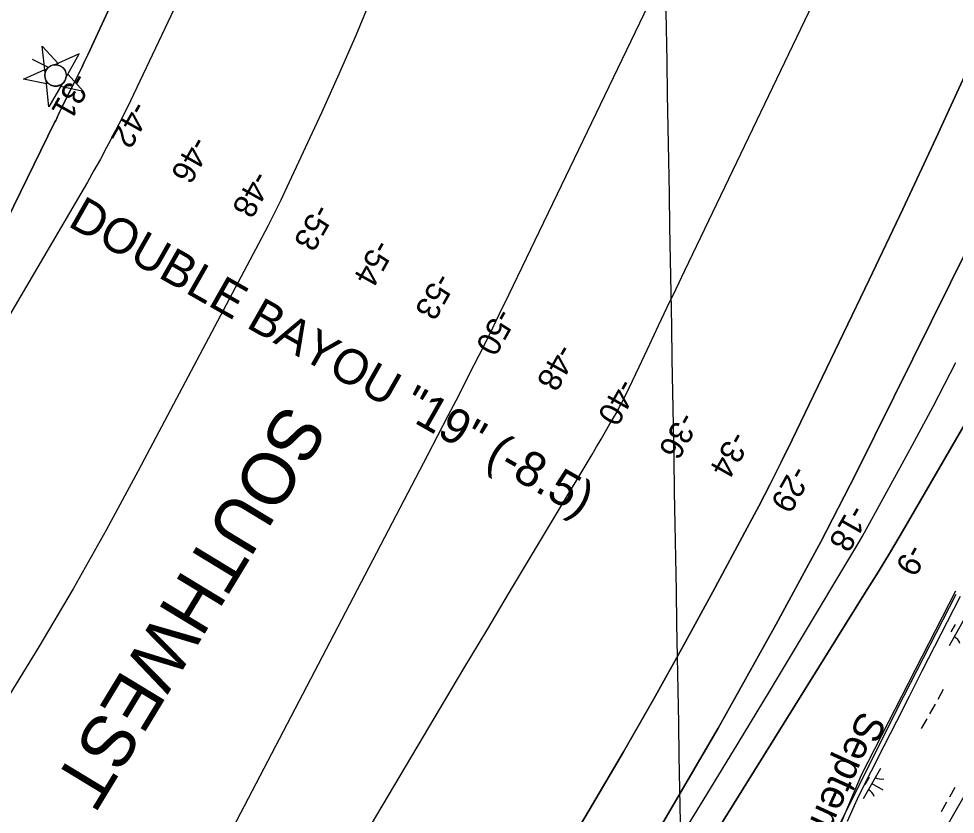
# Model space of a CAD drawing. Extents: x 3913936 to 3933962, y 195330 to 217741.
# Drawn here: x 3924311 to 3925651, y 203527 to 204666 of the extents above; entities that cross this region are included whole.
import ezdxf

# ---------------------------------------------------------------- set-up
doc = ezdxf.new("R2010")
doc.units = 0
for name, color, linetype in [('V-CHAN-NAID', 7, 'Continuous'), ('V-GRID-MAJR', 7, 'Continuous'), ('V-LEVE-TOET', 7, 'Continuous'), ('V-RIVR-EDGE', 7, 'Continuous'), ('V-RIVR-IDEN', 7, 'Continuous'), ('V-RIVR-RANG', 7, 'Continuous'), ('V-RRAP-FSHR', 7, 'Continuous'), ('V-TOPO-DPTH', 7, 'Continuous'), ('V-TOPO-MAJR', 7, 'Continuous'), ('V-TOPO-MINR', 7, 'Continuous'), ('V-UTIL-LINE', 7, 'Continuous'), ('V-WETL-SWMP', 7, 'Continuous')]:
    doc.layers.add(name, color=color, linetype=linetype)

msp = doc.modelspace()

# ---------------------------------------------------------------- linework, layer by layer
at = {"layer": 'V-CHAN-NAID'}
for points in [[(3924348.6, 204588.4), (3924344.4, 204626.5), (3924367, 204601.7), (3924362.6, 204599.7), (3924362, 204599.7), (3924360.9, 204599.6), (3924360, 204599.4), (3924358.9, 204599.1), (3924358.1, 204598.8), (3924357.2, 204598.5), (3924356.4, 204598.1), (3924355.6, 204597.6), (3924354.7, 204597.1), (3924354, 204596.5), (3924353.4, 204596), (3924352.7, 204595.4), (3924351.9, 204594.6), (3924351.4, 204594), (3924350.8, 204593.2), (3924350.4, 204592.5), (3924349.9, 204591.7), (3924349.6, 204591), (3924349.2, 204590.2), (3924348.9, 204589.3)], [(3924378.5, 204582.3), (3924397.4, 204615.5), (3924362.6, 204599.7), (3924363.7, 204599.8), (3924364.6, 204599.7), (3924365.7, 204599.6), (3924366.7, 204599.4), (3924367.4, 204599.2), (3924368.2, 204599), (3924368.9, 204598.7), (3924369.6, 204598.4), (3924370.4, 204598.1), (3924371.1, 204597.7), (3924372, 204597.1), (3924372.6, 204596.7), (3924373.5, 204595.9), (3924374.2, 204595.3), (3924374.9, 204594.5), (3924375.5, 204593.8), (3924376, 204593.1), (3924376.5, 204592.4), (3924377, 204591.5), (3924377.4, 204590.7), (3924377.7, 204590), (3924377.9, 204589.2), (3924378.2, 204588.3), (3924378.3, 204587.7), (3924378.5, 204586.6), (3924378.6, 204585.8), (3924378.7, 204584.8), (3924378.7, 204583.8), (3924378.6, 204583)], [(3924349.9, 204577.4), (3924350.4, 204572.7), (3924317.6, 204579.4), (3924348.1, 204593.2), (3924348.6, 204588.4), (3924348.4, 204587.6), (3924348.3, 204586.8), (3924348.2, 204585.6), (3924348.1, 204584.6), (3924348.2, 204583.5), (3924348.3, 204582.5), (3924348.4, 204581.5), (3924348.6, 204580.7), (3924348.9, 204579.7), (3924349.2, 204578.8), (3924349.6, 204578)], [(3924378.5, 204582.3), (3924380.9, 204586.4), (3924403.4, 204561.7), (3924370.6, 204568.5), (3924373, 204572.6), (3924373.7, 204573.2), (3924374.4, 204573.9), (3924375.1, 204574.7), (3924375.8, 204575.5), (3924376.1, 204576), (3924376.5, 204576.7), (3924376.9, 204577.4), (3924377.2, 204578), (3924377.6, 204578.9), (3924377.9, 204579.6), (3924378.1, 204580.4), (3924378.3, 204581.2), (3924378.4, 204581.7)], [(3924373, 204572.6), (3924354.1, 204539.4), (3924349.9, 204577.4), (3924350.3, 204576.7), (3924350.9, 204575.8), (3924351.4, 204575.1), (3924352, 204574.3), (3924352.7, 204573.6), (3924353.3, 204573), (3924354.1, 204572.4), (3924354.7, 204571.9), (3924355.7, 204571.3), (3924356.6, 204570.8), (3924357.6, 204570.4), (3924358.4, 204570.1), (3924359.5, 204569.7), (3924360.6, 204569.5), (3924361.7, 204569.3), (3924362.4, 204569.3), (3924363.5, 204569.2), (3924364.5, 204569.3), (3924365.6, 204569.4), (3924366.6, 204569.6), (3924367.5, 204569.8), (3924368.5, 204570.1), (3924369.6, 204570.5), (3924370.5, 204571), (3924371.5, 204571.5), (3924372.1, 204572)]]:
    msp.add_lwpolyline(points, close=True, dxfattribs=at)
msp.add_circle((3924363.4, 204584.5), 15.3, dxfattribs=at)
at = {"layer": 'V-GRID-MAJR'}
msp.add_spline([(3925366, 197364), (3925326, 199633.5), (3925219.4, 205693.6), (3925112.7, 211753.6), (3925058.2, 214849.9)], degree=3, dxfattribs=at)
at = {"layer": 'V-LEVE-TOET'}
msp.add_line((3924330.1, 204607.7), (3924352.9, 204596.2), dxfattribs=at)
at = {"layer": 'V-RIVR-EDGE'}
msp.add_lwpolyline([(3925651.3, 203846.4), (3925516.5, 203583.5), (3925426.7, 203371.2), (3925377.2, 203253.2), (3925341.3, 203185.8), (3925264.9, 203062.2), (3925157, 202888.1), (3925098.6, 202758.9), (3925059.3, 202672.4)], dxfattribs=at)
at = {"layer": 'V-RRAP-FSHR'}
msp.add_lwpolyline([(3925496.8, 203517.3), (3925512.8, 203553.9), (3925531, 203589.5), (3925549.1, 203625.1), (3925567.3, 203660.8), (3925585.4, 203696.4), (3925603.6, 203732.8), (3925621.7, 203767.7), (3925639.9, 203803.4), (3925658.7, 203839.2)], dxfattribs=at)
at = {"layer": 'V-TOPO-DPTH'}
for points in [[(3924284.1, 204357.7), (3924362.2, 204517), (3924363.7, 204519.9), (3924365.1, 204522.9), (3924366.5, 204525.8), (3924367.8, 204528.8), (3924369.2, 204531.8), (3924370.6, 204534.8), (3924372, 204537.7), (3924373.4, 204540.7), (3924387.5, 204568.5), (3924390.3, 204574.1), (3924393.1, 204579.8), (3924395.9, 204585.5), (3924398.7, 204591.1), (3924401.5, 204596.8), (3924404.2, 204602.6), (3924406.9, 204608.3), (3924409.6, 204614), (3924768.7, 205391.8)], [(3924617.7, 204858.3), (3924470.8, 204548.4), (3924462.6, 204531.4), (3924454.2, 204514.6), (3924445.5, 204497.9), (3924436.6, 204481.3), (3924427.6, 204464.8), (3924418.4, 204448.3), (3924409, 204432), (3924399.6, 204415.7), (3923953.8, 203655.9)], [(3924617.7, 204858.3), (3924470.8, 204548.4), (3924462.6, 204531.4), (3924454.2, 204514.6), (3924445.5, 204497.9), (3924436.6, 204481.3), (3924427.6, 204464.8), (3924418.4, 204448.3), (3924409, 204432), (3924399.6, 204415.7), (3923953.8, 203655.9)], [(3924732.2, 203372.3), (3924947.9, 203735.7), (3924980.5, 203790.5), (3925013.2, 203845.3), (3925045.9, 203900), (3925078.7, 203954.7), (3925131.2, 204042.2), (3925137.7, 204053.1), (3925144.2, 204064.1), (3925150.6, 204075), (3925156.9, 204086), (3925167, 204103.4), (3925168.3, 204105.7), (3925169.5, 204108), (3925170.7, 204110.4), (3925171.9, 204112.7), (3925179.4, 204127.7), (3925184.3, 204137.6), (3925189.1, 204147.5), (3925193.9, 204157.5), (3925198.6, 204167.4), (3925214, 204200.2), (3925226.4, 204226.5), (3925238.9, 204252.8), (3925251.4, 204279.1), (3925264, 204305.4), (3925469.9, 204735.1)], [(3924732.2, 203372.3), (3924947.9, 203735.7), (3924980.5, 203790.5), (3925013.2, 203845.3), (3925045.9, 203900), (3925078.7, 203954.7), (3925131.2, 204042.2), (3925137.7, 204053.1), (3925144.2, 204064.1), (3925150.6, 204075), (3925156.9, 204086), (3925167, 204103.4), (3925168.3, 204105.7), (3925169.5, 204108), (3925170.7, 204110.4), (3925171.9, 204112.7), (3925179.4, 204127.7), (3925184.3, 204137.6), (3925189.1, 204147.5), (3925193.9, 204157.5), (3925198.6, 204167.4), (3925214, 204200.2), (3925226.4, 204226.5), (3925238.9, 204252.8), (3925251.4, 204279.1), (3925264, 204305.4), (3925469.9, 204735.1)], [(3924593.1, 202658.1), (3924654.6, 202753.8), (3924715.3, 202850.1), (3924775.5, 202946.7), (3924880.3, 203116.5), (3924887.6, 203128.5), (3924895, 203140.6), (3924902.2, 203152.7), (3924909.5, 203164.8), (3925132.1, 203541.3), (3925176.1, 203616.8), (3925219.5, 203692.6), (3925262, 203768.9), (3925304, 203845.6), (3925353.3, 203937.1), (3925369.9, 203968.4), (3925386.2, 203999.8), (3925402, 204031.4), (3925417.6, 204063.2), (3925527.9, 204292.2), (3925575.9, 204393.1), (3925623.3, 204494.2), (3925669.8, 204595.7)], [(3925669.8, 204595.7), (3925623.3, 204494.2), (3925575.9, 204393.1), (3925527.9, 204292.2), (3925417.6, 204063.2), (3925402, 204031.4), (3925386.2, 203999.8), (3925369.9, 203968.4), (3925353.3, 203937.1), (3925304, 203845.6), (3925262, 203768.9), (3925219.5, 203692.6), (3925176.1, 203616.8), (3925132.1, 203541.3), (3924909.5, 203164.8), (3924902.2, 203152.7), (3924895, 203140.6), (3924887.6, 203128.5), (3924880.3, 203116.5), (3924775.5, 202946.7), (3924715.3, 202850.1), (3924654.6, 202753.8), (3924593.1, 202658.1)], [(3924696.7, 202658.3), (3924745.2, 202729.8), (3924793.2, 202801.6), (3924840.5, 202873.9), (3924887.4, 202946.4), (3924966.3, 203069.7), (3924973.4, 203080.9), (3924980.4, 203092.2), (3924987.3, 203103.5), (3924994.1, 203114.8), (3925225.7, 203503.5), (3925268.9, 203577), (3925311.5, 203650.7), (3925353.3, 203725), (3925394.5, 203799.5), (3925441.1, 203884.9), (3925458.4, 203917.1), (3925475.4, 203949.5), (3925492.1, 203982), (3925508.6, 204014.6), (3925671.4, 204342.6)], [(3925671.4, 204342.6), (3925508.6, 204014.6), (3925492.1, 203982), (3925475.4, 203949.5), (3925458.4, 203917.1), (3925441.1, 203884.9), (3925394.5, 203799.5), (3925353.3, 203725), (3925311.5, 203650.7), (3925268.9, 203577), (3925225.7, 203503.5), (3924994.1, 203114.8), (3924987.3, 203103.5), (3924980.4, 203092.2), (3924973.4, 203080.9), (3924966.3, 203069.7), (3924887.4, 202946.4), (3924840.5, 202873.9), (3924793.2, 202801.6), (3924745.2, 202729.8), (3924696.7, 202658.3)], [(3925808.3, 204333), (3925592.6, 203961.3), (3925575.5, 203932), (3925558.1, 203902.9), (3925540.5, 203873.9), (3925522.7, 203845), (3925146.7, 203241.2), (3925127.9, 203211.3), (3925109, 203181.4), (3925089.9, 203151.7), (3925070.7, 203122), (3925051.3, 203092.4), (3925031.9, 203062.9), (3925012.4, 203033.4), (3924992.9, 203004), (3924555, 202345.7)]]:
    msp.add_lwpolyline(points, dxfattribs=at)
at = {"layer": 'V-TOPO-MAJR'}
for points in [[(3924288.3, 202842.3), (3924311.6, 202889.1), (3924334.6, 202936), (3924345.5, 202958.7), (3924373.6, 203017.2), (3924401.7, 203075.6), (3924429.9, 203134), (3924458, 203192.4), (3924496.6, 203272.3), (3924511.1, 203302.1), (3924525.8, 203331.8), (3924540.9, 203361.4), (3924556.1, 203390.8), (3924895.7, 204040.5), (3924910.6, 204069.2), (3924925.5, 204097.9), (3924940.4, 204126.7), (3924955.1, 204155.5), (3924969.8, 204184.4), (3924984.3, 204213.3), (3924998.5, 204242.3), (3925012.7, 204271.5), (3925230.7, 204724.8)], [(3924816.1, 204697.6), (3924793, 204641.6), (3924768.9, 204586.2), (3924744, 204531.1), (3924694.5, 204424.6), (3924685.8, 204406.2), (3924676.9, 204388), (3924667.7, 204369.9), (3924658.4, 204351.9), (3924481.8, 204018.6), (3924435.8, 203933.9), (3924388.5, 203849.9), (3924339.5, 203766.9), (3924289.2, 203684.6)]]:
    msp.add_lwpolyline(points, dxfattribs=at)
at = {"layer": 'V-TOPO-MINR'}
for points in [[(3924768.7, 205391.8), (3924409.6, 204614), (3924406.9, 204608.3), (3924404.2, 204602.6), (3924401.5, 204596.8), (3924398.7, 204591.1), (3924395.9, 204585.5), (3924393.1, 204579.8), (3924390.3, 204574.1), (3924387.5, 204568.5), (3924373.4, 204540.7), (3924372, 204537.7), (3924370.6, 204534.8), (3924369.2, 204531.8), (3924367.8, 204528.8), (3924366.5, 204525.8), (3924365.1, 204522.9), (3924363.7, 204519.9), (3924362.2, 204517), (3924284.1, 204357.7)], [(3924617.7, 204858.3), (3924470.8, 204548.4), (3924462.6, 204531.4), (3924454.2, 204514.6), (3924445.5, 204497.9), (3924436.6, 204481.3), (3924427.6, 204464.8), (3924418.4, 204448.3), (3924409, 204432), (3924399.6, 204415.7), (3923953.8, 203655.9)], [(3924732.2, 203372.3), (3924947.9, 203735.7), (3924980.5, 203790.5), (3925013.2, 203845.3), (3925045.9, 203900), (3925078.7, 203954.7), (3925131.2, 204042.2), (3925137.7, 204053.1), (3925144.2, 204064.1), (3925150.6, 204075), (3925156.9, 204086), (3925167, 204103.4), (3925168.3, 204105.7), (3925169.5, 204108), (3925170.7, 204110.4), (3925171.9, 204112.7), (3925179.4, 204127.7), (3925184.3, 204137.6), (3925189.1, 204147.5), (3925193.9, 204157.5), (3925198.6, 204167.4), (3925214, 204200.2), (3925226.4, 204226.5), (3925238.9, 204252.8), (3925251.4, 204279.1), (3925264, 204305.4), (3925469.9, 204735.1)], [(3924593.1, 202658.1), (3924654.6, 202753.8), (3924715.3, 202850.1), (3924775.5, 202946.7), (3924880.3, 203116.5), (3924887.6, 203128.5), (3924895, 203140.6), (3924902.2, 203152.7), (3924909.5, 203164.8), (3925132.1, 203541.3), (3925176.1, 203616.8), (3925219.5, 203692.6), (3925262, 203768.9), (3925304, 203845.6), (3925353.3, 203937.1), (3925369.9, 203968.4), (3925386.2, 203999.8), (3925402, 204031.4), (3925417.6, 204063.2), (3925527.9, 204292.2), (3925575.9, 204393.1), (3925623.3, 204494.2), (3925669.8, 204595.7)], [(3924696.7, 202658.3), (3924745.2, 202729.8), (3924793.2, 202801.6), (3924840.5, 202873.9), (3924887.4, 202946.4), (3924966.3, 203069.7), (3924973.4, 203080.9), (3924980.4, 203092.2), (3924987.3, 203103.5), (3924994.1, 203114.8), (3925225.7, 203503.5), (3925268.9, 203577), (3925311.5, 203650.7), (3925353.3, 203725), (3925394.5, 203799.5), (3925441.1, 203884.9), (3925458.4, 203917.1), (3925475.4, 203949.5), (3925492.1, 203982), (3925508.6, 204014.6), (3925671.4, 204342.6)], [(3924555, 202345.7), (3924992.9, 203004), (3925012.4, 203033.4), (3925031.9, 203062.9), (3925051.3, 203092.4), (3925070.7, 203122), (3925089.9, 203151.7), (3925109, 203181.4), (3925127.9, 203211.3), (3925146.7, 203241.2), (3925522.7, 203845), (3925540.5, 203873.9), (3925558.1, 203902.9), (3925575.5, 203932), (3925592.6, 203961.3), (3925808.3, 204333)], [(3924758.5, 202702.9), (3924974.3, 203036.4), (3924988.3, 203058.1), (3925002.1, 203079.8), (3925015.8, 203101.7), (3925029.4, 203123.6), (3925250.1, 203481.7), (3925295.3, 203555.4), (3925340.3, 203629.1), (3925385, 203703), (3925429.6, 203777), (3925507.2, 203906.6), (3925512.8, 203916), (3925518.2, 203925.4), (3925523.6, 203934.8), (3925528.9, 203944.3), (3925586.1, 204048.9), (3925619.3, 204111), (3925651.6, 204173.6)]]:
    msp.add_lwpolyline(points, dxfattribs=at)
at = {"layer": 'V-UTIL-LINE'}
msp.add_lwpolyline([(3927650.4, 207012.8), (3925143.7, 202648.2), (3924419.5, 201771.6), (3924393.5, 201817.6)], dxfattribs=at)
at = {"layer": 'V-WETL-SWMP'}
for p, q in [((3925666.7, 203811.8), (3925642.2, 203768.2)), ((3925650.7, 203799), (3925644.8, 203788.5)), ((3925633.8, 203705.8), (3925625.9, 203691.8)), ((3925622, 203684.9), (3925614.2, 203670.9)), ((3925610.3, 203663.9), (3925602.4, 203650)), ((3925543.8, 203593), (3925519.3, 203549.4)), ((3925527.7, 203580.2), (3925521.8, 203569.8)), ((3925531.5, 203571.2), (3925547.2, 203562.4)), ((3925650.3, 203565.7), (3925642.5, 203551.8)), ((3925638.6, 203544.8), (3925630.7, 203530.8))]:
    msp.add_line(p, q, dxfattribs=at)
msp.add_lwpolyline([(3925651.8, 203841.6), (3925576.7, 203696.1), (3925488.1, 203518.9), (3925426.2, 203360.3), (3925390.1, 203269.6), (3925363.1, 203212.2), (3925335.4, 203163.4), (3925311.5, 203124.6), (3925253.2, 203040.4), (3925171.1, 202909.3), (3925146.8, 202873.6), (3925129.9, 202844.1), (3925121.8, 202829.4), (3925107.9, 202800.3), (3925061.3, 202698.7)], dxfattribs=at)
for centre, start, end in [((3925641.2, 203765.8), 19.8861, 61.4297), ((3925545.2, 203595.2), 239.8861, 281.4297), ((3925518.2, 203547), 19.8861, 61.4297)]:
    msp.add_arc(centre, 17.6, start, end, dxfattribs=at)

# ---------------------------------------------------------------- texts
at = {"layer": 'V-CHAN-NAID'}
msp.add_text('DOUBLE BAYOU "19" (-8.5)', height=50, rotation=330.4055, dxfattribs=at).set_placement((3924379.5, 204369.9))
at = {"layer": 'V-RIVR-IDEN'}
for s, height, rotation, p in [('SOUTHWEST ', 75, 238.737, (3924690.9, 204117.8)), ('September 2012', 42, 245.3769, (3925515.5, 203677.3))]:
    msp.add_text(s, height=height, rotation=rotation, dxfattribs=at).set_placement(p)
at = {"layer": 'V-RIVR-RANG'}
for s, rotation, p in [('-31', 240.7035, (3924388.2, 204591.1)), ('-42', 240.7035, (3924473.2, 204550.2)), ('-46', 240.7035, (3924559.3, 204499.8)), ('-48', 240.7035, (3924646.8, 204450.4)), ('-53', 240.7035, (3924735.1, 204402.9)), ('-54', 240.7035, (3924821.1, 204352.1)), ('-53', 240.7035, (3924908.5, 204304.4)), ('-50', 240.7035, (3924995.4, 204253.6)), ('-48', 240.7035, (3925082.6, 204202.7)), ('-40', 240.7035, (3925169.8, 204153.3)), ('-36', 240.7035, (3925257.3, 204105.2)), ('-34', 240.4483, (3925330.8, 204078)), ('-29', 240.4483, (3925417.8, 204028.6)), ('-18', 240.4483, (3925501, 203972.5)), ('-9', 240.4483, (3925584.1, 203916.4))]:
    msp.add_text(s, height=33.5, rotation=rotation, dxfattribs=at).set_placement(p)

doc.saveas('drawing.dxf')
